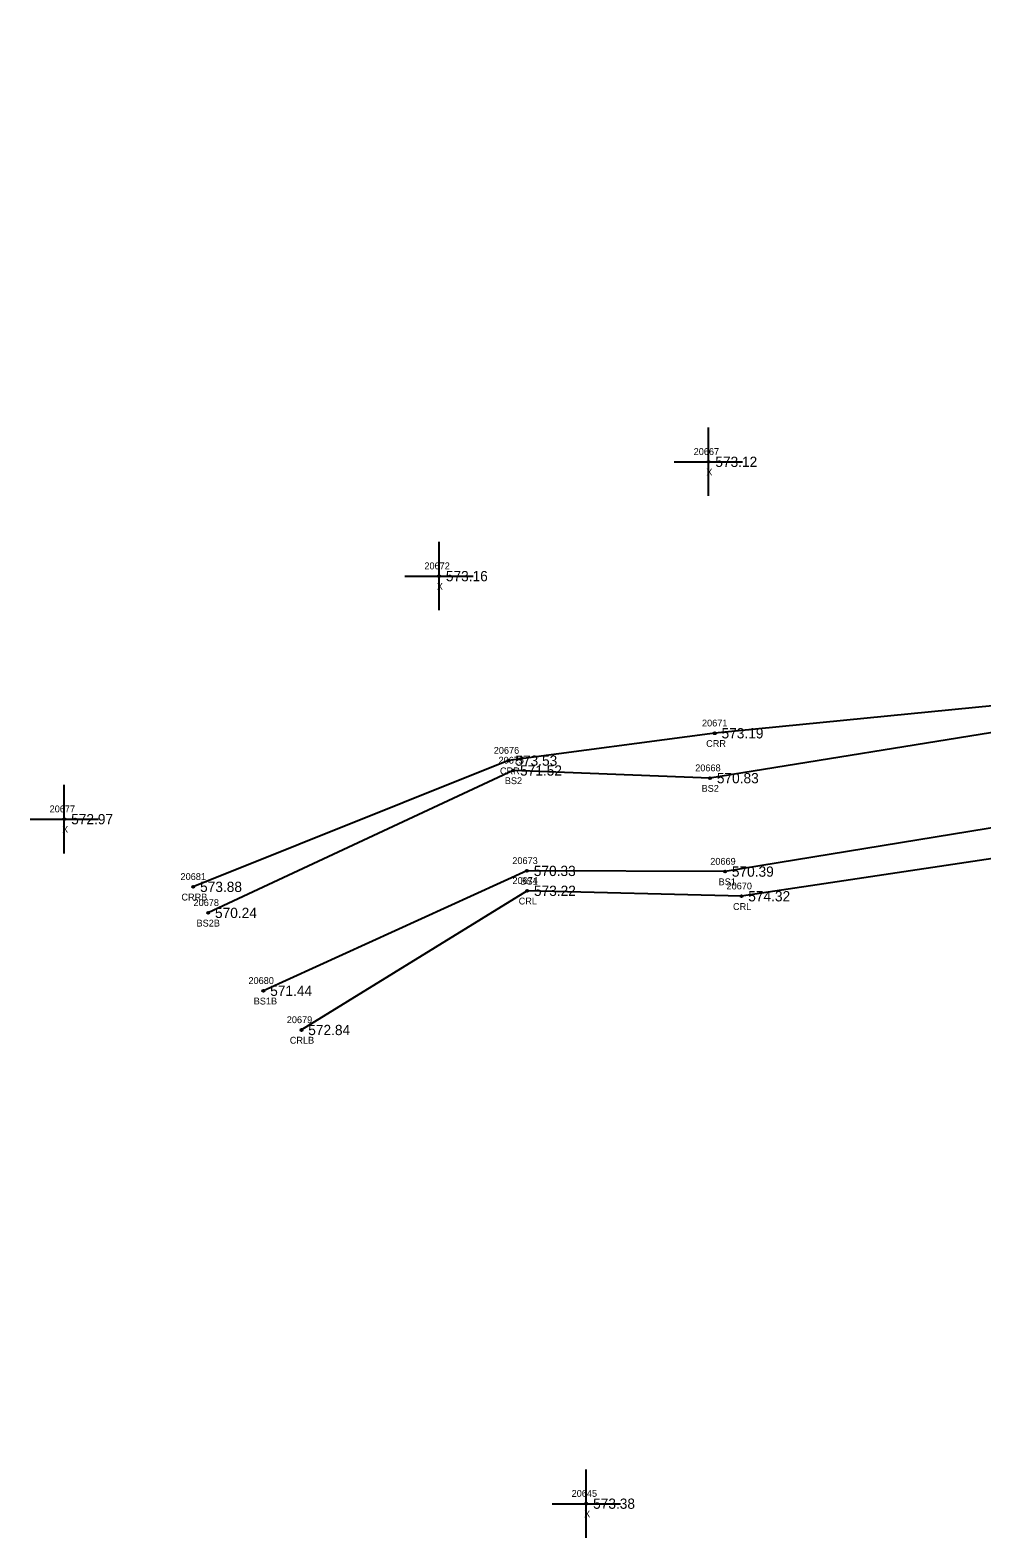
# Model space of a CAD drawing. Extents: x 1664837 to 1666270, y 987403 to 988245.
# Drawn here: x 1665023 to 1665162.3, y 987511.9 to 987732.4 of the extents above; entities that cross this region are included whole.
import ezdxf

# ---------------------------------------------------------------- set-up
doc = ezdxf.new("R2010")
doc.units = 0
for name, color, linetype in [('RD_DTM_BkLn2', 7, 'Continuous'), ('RD_DTM_BkLn_txCode', 7, 'Continuous'), ('RD_EX_H2O', 7, 'Continuous'), ('RD_EX_H2O_txCode', 7, 'Continuous'), ('RD_EX_Misc', 7, 'Continuous'), ('RD_EX_Misc_txCode', 7, 'Continuous'), ('RD_EX_TX_H2O_ELEV', 7, 'Continuous'), ('RD_EX_TX_Misc_ELEV', 7, 'Continuous'), ('RD_SMD_Locator', 7, 'Continuous')]:
    doc.layers.add(name, color=color, linetype=linetype)

msp = doc.modelspace()

# ---------------------------------------------------------------- linework, layer by layer
at = {"layer": 'RD_DTM_BkLn2'}
for points in [[(1665511.23, 987778.14), (1665500.12, 987754.08), (1665496.26, 987735.63), (1665475.45, 987718.43), (1665445.39, 987709.52), (1665428.04, 987704.31), (1665389.45, 987688.17), (1665361.39, 987673.13), (1665330.12, 987656.7), (1665283.57, 987647.17), (1665235.53, 987667.53), (1665208.93, 987663.65), (1665168.4, 987630.38), (1665122.54, 987622.98), (1665093.74, 987624.1), (1665049.09, 987603.27)], [(1665468.58, 987700.71), (1665465.66, 987702.55), (1665430.48, 987698.85), (1665398.05, 987680.55), (1665367.06, 987661.74), (1665332.15, 987651.54), (1665283, 987639.17), (1665233.73, 987658.08), (1665210.97, 987648.76), (1665173.41, 987617.25), (1665124.74, 987609.31), (1665095.75, 987609.41), (1665057.17, 987591.87)]]:
    msp.add_lwpolyline(points, dxfattribs=at)
at = {"layer": 'RD_EX_H2O'}
for points in [[(1665498.75, 987759.37), (1665497.35, 987756.86), (1665493.15, 987755.47), (1665489.09, 987748.98), (1665492.34, 987734.97), (1665472.46, 987721.68), (1665444.71, 987712.07), (1665426.39, 987705.52), (1665387.14, 987692.07), (1665353.81, 987678.17), (1665328.18, 987659.89), (1665283.87, 987652.21), (1665224.39, 987676.29), (1665206.47, 987666.98), (1665167.33, 987633.9), (1665123.23, 987629.54), (1665093.05, 987625.54), (1665046.91, 987607.08)], [(1665465.98, 987698.59), (1665465.01, 987698.79), (1665432.65, 987694.17), (1665400.81, 987677.37), (1665370.11, 987653.55), (1665334.58, 987643.2), (1665283.82, 987631.84), (1665232.68, 987646.81), (1665216.29, 987640.35), (1665180.84, 987613.76), (1665127.14, 987605.7), (1665095.77, 987606.5), (1665062.74, 987586.14)]]:
    msp.add_lwpolyline(points, dxfattribs=at)
at = {"layer": 'RD_EX_Misc'}
for p, q in [((1665122.32, 987664.25), (1665122.32, 987674.25)), ((1665117.32, 987669.25), (1665127.32, 987669.25)), ((1665082.88, 987647.53), (1665082.88, 987657.53)), ((1665077.88, 987652.53), (1665087.88, 987652.53)), ((1665028.04, 987611.98), (1665028.04, 987621.98)), ((1665023.04, 987616.98), (1665033.04, 987616.98)), ((1665104.43, 987511.85), (1665104.43, 987521.85)), ((1665099.43, 987516.85), (1665109.43, 987516.85))]:
    msp.add_line(p, q, dxfattribs=at)
at = {"layer": 'RD_SMD_Locator'}
for centre in [(1665122.32, 987669.25), (1665082.88, 987652.53), (1665123.23, 987629.54), (1665093.05, 987625.54), (1665093.74, 987624.1), (1665122.54, 987622.98), (1665028.04, 987616.98), (1665095.75, 987609.41), (1665124.74, 987609.31), (1665046.91, 987607.08), (1665095.77, 987606.5), (1665127.14, 987605.7), (1665049.09, 987603.27), (1665057.17, 987591.87), (1665062.74, 987586.14), (1665104.43, 987516.85)]:
    msp.add_circle(centre, 0.15, dxfattribs=at)

# ---------------------------------------------------------------- texts
at = {"layer": 'RD_DTM_BkLn_txCode'}
for s, p in [('20675', (1665091.59, 987625.1)), ('20668', (1665120.38, 987623.98)), ('BS2', (1665092.51, 987622.1)), ('BS2', (1665121.31, 987620.98)), ('20673', (1665093.61, 987610.41)), ('20669', (1665122.58, 987610.31)), ('BS1', (1665094.8, 987607.41)), ('BS1', (1665123.8, 987607.31)), ('20678', (1665046.95, 987604.27)), ('BS2B', (1665047.39, 987601.27)), ('20680', (1665054.99, 987592.87)), ('BS1B', (1665055.76, 987589.87))]:
    msp.add_text(s, height=1, dxfattribs=at).set_placement(p)
at = {"layer": 'RD_EX_H2O_txCode'}
for s, p in [('20671', (1665121.37, 987630.54)), ('20676', (1665090.89, 987626.54)), ('CRR', (1665121.98, 987627.54)), ('CRR', (1665091.8, 987623.54)), ('20681', (1665045.05, 987608.08)), ('20674', (1665093.63, 987607.5)), ('20670', (1665124.96, 987606.7)), ('CRRB', (1665045.18, 987605.08)), ('CRL', (1665094.54, 987604.5)), ('CRL', (1665125.91, 987603.7)), ('20679', (1665060.6, 987587.14)), ('CRLB', (1665061.04, 987584.14))]:
    msp.add_text(s, height=1, dxfattribs=at).set_placement(p)
at = {"layer": 'RD_EX_Misc_txCode'}
for s, p in [('20667', (1665120.15, 987670.25)), ('X', (1665122, 987667.25)), ('20672', (1665080.74, 987653.53)), ('X', (1665082.56, 987650.53)), ('20677', (1665025.89, 987617.98)), ('X', (1665027.72, 987614.98)), ('20645', (1665102.29, 987517.85)), ('X', (1665104.12, 987514.85))]:
    msp.add_text(s, height=1, dxfattribs=at).set_placement(p)
at = {"layer": 'RD_EX_TX_H2O_ELEV'}
for s, p in [('573.19', (1665124.23, 987628.79)), ('573.53', (1665094.05, 987624.79)), ('573.88', (1665047.91, 987606.33)), ('573.22', (1665096.77, 987605.75)), ('574.32', (1665128.14, 987604.95)), ('572.84', (1665063.74, 987585.39))]:
    msp.add_text(s, height=1.5, dxfattribs=at).set_placement(p)
at = {"layer": 'RD_EX_TX_Misc_ELEV'}
for s, p in [('573.12', (1665123.32, 987668.5)), ('573.16', (1665083.88, 987651.78)), ('571.52', (1665094.74, 987623.35)), ('570.83', (1665123.54, 987622.23)), ('572.97', (1665029.04, 987616.23)), ('570.33', (1665096.75, 987608.66)), ('570.39', (1665125.74, 987608.56)), ('570.24', (1665050.09, 987602.52)), ('571.44', (1665058.17, 987591.12)), ('573.38', (1665105.43, 987516.1))]:
    msp.add_text(s, height=1.5, dxfattribs=at).set_placement(p)

doc.saveas('drawing.dxf')
